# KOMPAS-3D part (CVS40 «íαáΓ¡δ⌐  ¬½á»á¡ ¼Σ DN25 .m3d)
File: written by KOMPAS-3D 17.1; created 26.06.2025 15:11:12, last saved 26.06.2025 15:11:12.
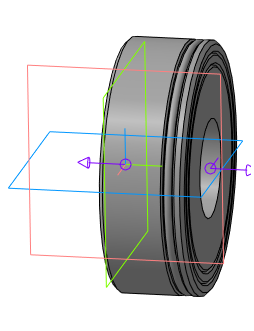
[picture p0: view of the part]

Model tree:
1. Эскиз:1
2. Элемент вращения:1
     Угол 1 = 360
3. Присоединительная точка:1
4. Присоединительная точка:2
